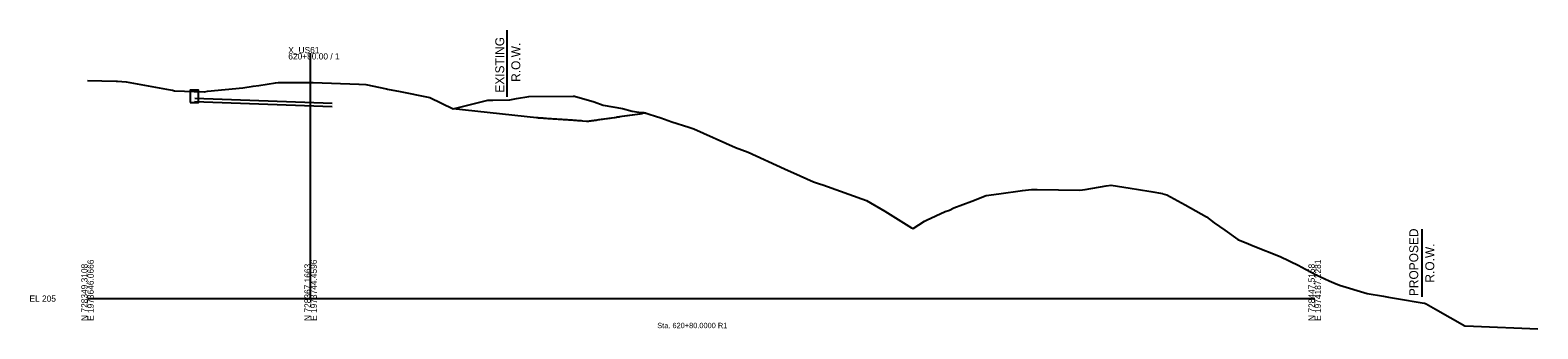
# Model space of a CAD drawing. Extents: x -26 to 1629, y -25 to 9635.
# Drawn here: x -26 to 650, y 1986 to 2120 of the extents above; entities that cross this region are included whole.
import ezdxf

# ---------------------------------------------------------------- set-up
doc = ezdxf.new("R2010")
doc.units = 0
for name, color, linetype in [('Draft_XS_Grid', 7, 'Continuous'), ('Draft_XS_Text', 7, 'Continuous'), ('DTM_X_GROUND', 7, 'Continuous'), ('XS_CELL', 7, 'Continuous'), ('XS_P_GROUND', 7, 'Continuous'), ('XS_P_ROW', 7, 'Continuous'), ('XS_X_DRAINAGE', 7, 'Continuous'), ('XS_X_ROW', 7, 'Continuous')]:
    doc.layers.add(name, color=color, linetype=linetype)

msp = doc.modelspace()

# ---------------------------------------------------------------- linework, layer by layer
at = {"layer": 'DTM_X_GROUND'}
msp.add_lwpolyline([(0, 2097.73), (12.86, 2097.54), (13.41, 2097.53), (13.44, 2097.53), (17.33, 2097.23), (35.46, 2093.9), (38.1, 2093.39), (38.94, 2093.2), (52.25, 2092.73), (52.44, 2092.76), (53.76, 2092.95), (69.67, 2094.49), (74.23, 2095.2), (76.82, 2095.59), (84.27, 2096.74), (85.48, 2096.81), (87.19, 2096.9), (94.99, 2096.9), (101.11, 2096.91), (121.67, 2096.2), (121.71, 2096.2), (121.72, 2096.2), (124.77, 2095.91), (133.96, 2094.03), (134.39, 2093.94), (135.27, 2093.75), (139.43, 2092.92), (153.39, 2090.13), (163.92, 2085.09), (179.38, 2089.02), (181.67, 2088.95), (189.27, 2089.1), (192.27, 2089.75), (197.81, 2090.61), (217.7, 2090.8), (218.09, 2090.8), (218.22, 2090.76), (227.04, 2088.15), (231.09, 2086.68), (239.73, 2085.21), (244.13, 2084.06), (247.11, 2083.53), (248.98, 2083.46), (249.36, 2083.43), (256.91, 2081.08), (261.85, 2079.31), (269.47, 2076.8), (271.78, 2076.04), (290.42, 2067.8), (296.05, 2065.7), (312.41, 2058.1), (319.46, 2055.01), (325.3, 2052.39), (328.03, 2051.38), (329.49, 2050.93), (349.08, 2043.91), (357.41, 2039.19), (369.3, 2031.71), (370.03, 2031.36), (375.19, 2034.75), (376, 2035.11), (384.4, 2039.1), (386.28, 2039.67), (388.32, 2040.67), (396.32, 2043.67), (402.74, 2046.17), (408.37, 2046.9), (419, 2048.48), (423.13, 2048.86), (423.48, 2048.87), (424.2, 2048.9), (425.56, 2048.97), (444.75, 2048.57), (447.13, 2048.98), (456.48, 2050.59), (458.71, 2050.88), (467.23, 2049.54), (470.99, 2048.91), (476.58, 2048.01), (481.72, 2047.1), (481.94, 2047.04), (483.78, 2046.59), (491.87, 2042.07), (501.43, 2036.71), (504.94, 2034.02), (509.74, 2030.74), (515.53, 2026.53), (515.8, 2026.39), (517.01, 2025.85), (520.37, 2024.6), (521.44, 2024.12), (522.43, 2023.6), (534.59, 2018.88), (542.84, 2014.83), (543.92, 2014.21), (546.17, 2013.02), (550.64, 2010.64), (556.52, 2008), (558.58, 2007.02), (561.07, 2006.05), (573.5, 2002.23), (580.83, 2001.07), (583, 2000.6), (586.63, 2000), (599.07, 1997.93), (599.23, 1997.9), (599.66, 1997.84), (599.97, 1997.65), (604.19, 1995.25), (617.24, 1987.86), (621.17, 1987.61), (650, 1986.44)], dxfattribs=at)
msp.add_lwpolyline([(0, 2097.73), (12.86, 2097.54), (13.41, 2097.53), (13.44, 2097.53), (17.33, 2097.23), (35.46, 2093.9), (38.1, 2093.39), (38.94, 2093.2), (52.25, 2092.73), (52.44, 2092.76), (53.76, 2092.95), (69.67, 2094.49), (74.23, 2095.2), (76.82, 2095.59), (84.27, 2096.74), (85.48, 2096.81), (87.19, 2096.9), (94.99, 2096.9), (101.11, 2096.91), (121.67, 2096.2), (121.71, 2096.2), (121.72, 2096.2), (124.77, 2095.91), (133.96, 2094.03), (134.39, 2093.94), (135.27, 2093.75), (139.43, 2092.92), (153.39, 2090.13), (163.92, 2085.09), (179.38, 2089.02), (181.67, 2088.95), (189.27, 2089.1), (192.27, 2089.75), (197.81, 2090.61), (217.7, 2090.8), (218.09, 2090.8), (218.22, 2090.76), (227.04, 2088.15), (231.09, 2086.68), (239.73, 2085.21), (244.13, 2084.06), (247.11, 2083.53), (248.98, 2083.46), (249.36, 2083.43), (256.91, 2081.08), (261.85, 2079.31), (269.47, 2076.8), (271.78, 2076.04), (290.42, 2067.8), (296.05, 2065.7), (312.41, 2058.1), (319.46, 2055.01), (325.3, 2052.39), (328.03, 2051.38), (329.49, 2050.93), (349.08, 2043.91), (357.41, 2039.19), (369.3, 2031.71), (370.03, 2031.36), (375.19, 2034.75), (376, 2035.11), (384.4, 2039.1), (386.28, 2039.67), (388.32, 2040.67), (396.32, 2043.67), (402.74, 2046.17), (408.37, 2046.9), (419, 2048.48), (423.13, 2048.86), (423.48, 2048.87), (424.2, 2048.9), (425.56, 2048.97), (444.75, 2048.57), (447.13, 2048.98), (456.48, 2050.59), (458.71, 2050.88), (467.23, 2049.54), (470.99, 2048.91), (476.58, 2048.01), (481.72, 2047.1), (481.94, 2047.04), (483.78, 2046.59), (491.87, 2042.07), (501.43, 2036.71), (504.94, 2034.02), (509.74, 2030.74), (515.53, 2026.53), (515.8, 2026.39), (517.01, 2025.85), (520.37, 2024.6), (521.44, 2024.12), (522.43, 2023.6), (534.59, 2018.88), (542.84, 2014.83), (543.92, 2014.21), (546.17, 2013.02), (550.64, 2010.64), (556.52, 2008), (558.58, 2007.02), (561.07, 2006.05), (573.5, 2002.23), (580.83, 2001.07), (583, 2000.6), (586.63, 2000), (599.07, 1997.93), (599.23, 1997.9), (599.66, 1997.84), (599.97, 1997.65), (604.19, 1995.25), (617.24, 1987.86), (621.17, 1987.61), (650, 1986.44)], dxfattribs=at)
at = {"layer": 'XS_CELL'}
for p, q in [((100, 2000), (100, 2110)), ((0, 2000), (100, 2000)), ((100, 2000), (550, 2000))]:
    msp.add_line(p, q, dxfattribs=at)
at = {"layer": 'XS_P_GROUND'}
msp.add_line((201.25, 2081.01), (163.92, 2085.09), dxfattribs=at)
msp.add_lwpolyline([(250.32, 2083.13), (249.9, 2083.07), (249.89, 2083.07), (248.76, 2082.91), (248.73, 2082.9), (247.63, 2082.75), (247.56, 2082.74), (246.5, 2082.58), (246.41, 2082.57), (245.36, 2082.42), (245.26, 2082.4), (244.23, 2082.26), (244.1, 2082.24), (243.1, 2082.09), (242.93, 2082.07), (241.96, 2081.93), (241.78, 2081.9), (240.83, 2081.77), (240.62, 2081.74), (239.7, 2081.6), (239.47, 2081.57), (238.56, 2081.44), (238.31, 2081.4), (237.43, 2081.28), (237.16, 2081.24), (236.3, 2081.11), (236.01, 2081.07), (235.16, 2080.95), (234.85, 2080.9), (234.03, 2080.79), (233.7, 2080.74), (232.9, 2080.62), (232.55, 2080.57), (231.76, 2080.46), (231.39, 2080.41), (230.63, 2080.3), (230.24, 2080.24), (229.5, 2080.13), (229.09, 2080.07), (228.36, 2079.97), (227.93, 2079.91), (227.23, 2079.81), (226.78, 2079.74), (226.1, 2079.64), (225.62, 2079.57), (224.96, 2079.48), (224.47, 2079.41), (223.83, 2079.32), (221.99, 2079.61), (221.46, 2079.64), (220.92, 2079.68), (220.31, 2079.72), (219.75, 2079.76), (219.15, 2079.8), (218.57, 2079.84), (218, 2079.88), (217.4, 2079.92), (216.84, 2079.95), (216.23, 2080), (215.69, 2080.03), (215.06, 2080.08), (214.53, 2080.11), (213.89, 2080.16), (213.38, 2080.19), (212.72, 2080.23), (212.23, 2080.27), (211.54, 2080.31), (211.07, 2080.35), (210.37, 2080.39), (209.92, 2080.42), (209.2, 2080.47), (208.76, 2080.5), (208.03, 2080.55), (207.61, 2080.58), (206.85, 2080.63), (206.45, 2080.66), (205.68, 2080.71), (205.3, 2080.74), (204.51, 2080.79), (204.14, 2080.82), (203.33, 2080.87), (202.99, 2080.89), (202.16, 2080.95), (201.84, 2080.97), (201.41, 2081), (201.25, 2081.01)], dxfattribs=at)
at = {"layer": 'XS_P_ROW'}
msp.add_line((598, 2031.07), (598, 2000.75), dxfattribs=at)
at = {"layer": 'XS_X_DRAINAGE'}
for p, q in [((48, 2088.4), (109.63, 2086.06)), ((48.06, 2089.9), (109.68, 2087.56))]:
    msp.add_line(p, q, dxfattribs=at)
msp.add_lwpolyline([(45.96, 2087.88), (49.76, 2087.88), (49.76, 2093.44), (45.96, 2093.44)], close=True, dxfattribs=at)
at = {"layer": 'XS_X_ROW'}
msp.add_line((188, 2120.34), (188, 2090.45), dxfattribs=at)

# ---------------------------------------------------------------- texts
at = {"layer": 'Draft_XS_Grid'}
msp.add_text('-', height=0.0001, dxfattribs=at).set_placement((0, 2000))
at = {"layer": 'Draft_XS_Text'}
msp.add_text('Sta. 620+80.0000 R1', height=2.4, dxfattribs=at).set_placement((255.34, 1986.75))
at = {"layer": 'XS_CELL'}
for s, p in [('X_US61', (90, 2110)), ('620+80.00 / 1', (90, 2107.2)), ('EL 205', (-26, 1998.6))]:
    msp.add_text(s, height=2.8, dxfattribs=at).set_placement(p)
for s, p in [('N 728349.3108', (0, 1990)), ('E 1973646.0666', (2.8, 1990)), ('N 728367.1663', (100, 1990)), ('E 1973744.4596', (102.8, 1990)), ('N 728447.5158', (550, 1990)), ('E 1974187.2281', (552.8, 1990))]:
    msp.add_text(s, height=2.8, rotation=90, dxfattribs=at).set_placement(p)
at = {"layer": 'XS_P_ROW'}
for s, p in [('PROPOSED', (596.37, 2001.11)), ('R.O.W.', (603.57, 2007.18))]:
    msp.add_text(s, height=4, rotation=90, dxfattribs=at).set_placement(p)
at = {"layer": 'XS_X_ROW'}
for s, p in [('EXISTING', (186.76, 2092.32)), ('R.O.W.', (193.96, 2097.17))]:
    msp.add_text(s, height=4, rotation=90, dxfattribs=at).set_placement(p)

doc.saveas('drawing.dxf')
